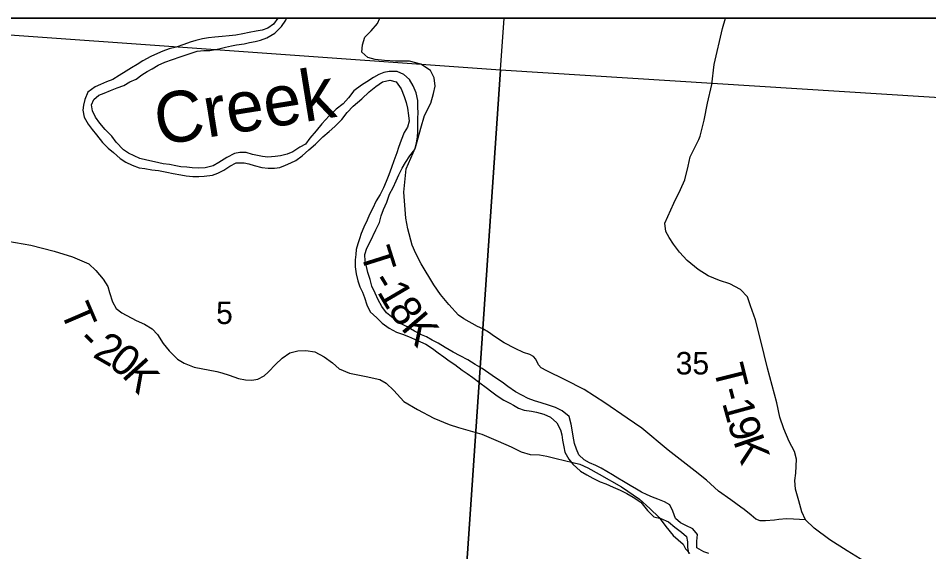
# Model space of a CAD drawing. Extents: x 0 to 34, y 0 to 22.
# Drawn here: x 3.709 to 5.404, y 19.906 to 20.9 of the extents above; entities that cross this region are included whole.
import ezdxf

# ---------------------------------------------------------------- set-up
doc = ezdxf.new("R2010")
doc.units = 0
for name, color, linetype in [('GM_X_Corporation', 7, 'Continuous'), ('GM_X_Major_River', 7, 'Continuous'), ('GM_X_Major_River_Text', 7, 'Continuous'), ('GM_X_Section_Text', 7, 'Continuous'), ('GM_X_Township_Road', 7, 'Continuous'), ('GM_X_Township_Road_Text', 7, 'Continuous'), ('SH_Data', 7, 'Continuous')]:
    doc.layers.add(name, color=color, linetype=linetype)

msp = doc.modelspace()

# ---------------------------------------------------------------- linework, layer by layer
at = {"layer": 'GM_X_Corporation'}
msp.add_lwpolyline([(6.4774, 18.0202), (6.488, 18.1751), (6.5242, 18.7061), (6.5297, 18.7882), (6.5448, 18.981), (6.5455, 18.9878), (6.5461, 19.0017), (6.5463, 19.0089), (6.5469, 19.0218), (6.548, 19.0466), (6.5487, 19.0617), (6.5495, 19.082), (6.5503, 19.0966), (6.5514, 19.1091), (6.5523, 19.1179), (6.5529, 19.1264), (6.5537, 19.1382), (6.5541, 19.1447), (6.5536, 19.1514), (6.5814, 19.5334), (6.6608, 20.6694), (6.6768, 20.9), (2.1, 20.9), (2.1, 14.1)], dxfattribs=at)
for points in [[(4.614, 20.9), (3.608, 20.9), (3.6063, 20.8752), (4.607, 20.8038)], [(4.607, 20.8038), (4.5379, 19.7849), (3.5308, 19.8461), (3.6063, 20.8752)], [(5.6414, 20.7385), (5.5693, 19.7272), (4.5379, 19.7849), (4.607, 20.8038)]]:
    msp.add_lwpolyline(points, close=True, dxfattribs=at)
at = {"layer": 'GM_X_Major_River'}
for points in [[(4.1927, 20.9), (4.1845, 20.8889), (4.1739, 20.8813), (4.1636, 20.8775), (4.1522, 20.8756), (4.1393, 20.8734), (4.1276, 20.8707), (4.1147, 20.8685), (4.1021, 20.867), (4.0892, 20.8658), (4.0752, 20.8647), (4.0638, 20.8632), (4.0524, 20.8613), (4.0399, 20.8587), (4.0297, 20.8552), (4.0175, 20.8511), (4.0031, 20.8458), (3.9906, 20.8427), (3.9788, 20.8386), (3.9686, 20.834), (3.9564, 20.8287), (3.9416, 20.8204), (3.9306, 20.8139), (3.92, 20.8075), (3.9101, 20.8014), (3.8972, 20.7935), (3.8854, 20.7859), (3.8737, 20.7813), (3.8623, 20.7764), (3.8524, 20.7719), (3.8391, 20.7624), (3.8331, 20.7483), (3.8308, 20.7381), (3.8296, 20.7286), (3.8323, 20.7157), (3.8399, 20.7024), (3.8471, 20.6929), (3.8554, 20.683), (3.8664, 20.6686), (3.8767, 20.6576), (3.8869, 20.6499), (3.8994, 20.6389), (3.9097, 20.6317), (3.9214, 20.6264), (3.9347, 20.6214), (3.9449, 20.6199), (3.9582, 20.6176), (3.9707, 20.6161), (3.9863, 20.6134), (3.9977, 20.6107), (4.0121, 20.6081), (4.0223, 20.6065), (4.0345, 20.6054), (4.0455, 20.605), (4.0553, 20.6057), (4.0713, 20.6076), (4.0811, 20.6114), (4.0922, 20.6171), (4.1032, 20.6243), (4.1153, 20.6304), (4.1297, 20.6304), (4.1388, 20.6285), (4.1487, 20.6254), (4.1627, 20.6216), (4.1745, 20.6208), (4.1863, 20.6204), (4.1961, 20.622), (4.2071, 20.6261), (4.2166, 20.6307), (4.2261, 20.6352), (4.2382, 20.6439), (4.2504, 20.6546), (4.2629, 20.6656), (4.2766, 20.6788), (4.288, 20.6887), (4.299, 20.6982), (4.3119, 20.7111), (4.3218, 20.724), (4.3328, 20.7361), (4.3487, 20.7498), (4.3628, 20.7631), (4.3749, 20.7729), (4.3874, 20.7813), (4.4011, 20.7843), (4.4132, 20.7812), (4.4223, 20.7683), (4.428, 20.7539), (4.4314, 20.7429), (4.4337, 20.7322), (4.436, 20.7189), (4.4371, 20.7079), (4.4341, 20.6969)], [(4.4534, 20.7341), (4.4531, 20.7466), (4.45, 20.7611), (4.4447, 20.774), (4.4379, 20.7858), (4.4269, 20.7953), (4.4148, 20.8006), (4.4, 20.8006), (4.3901, 20.7987), (4.3806, 20.7949), (4.3704, 20.7892), (4.3582, 20.7817), (4.3483, 20.7752), (4.3339, 20.7646), (4.3244, 20.7517), (4.3142, 20.7403), (4.3009, 20.7305), (4.288, 20.7183), (4.2743, 20.7031), (4.2637, 20.6902), (4.2519, 20.6762), (4.2439, 20.6656), (4.2333, 20.6595), (4.2208, 20.6508), (4.2102, 20.6466), (4.1976, 20.6436), (4.1878, 20.6421), (4.1741, 20.641), (4.1643, 20.6421), (4.1453, 20.6463), (4.1339, 20.6497), (4.1218, 20.6501), (4.1119, 20.6478), (4.0975, 20.6403), (4.0827, 20.6312), (4.072, 20.6251), (4.0576, 20.6213), (4.0455, 20.6206), (4.033, 20.6213), (4.0235, 20.6225), (4.0121, 20.6233), (4.0026, 20.6252), (3.9909, 20.6275), (3.9791, 20.629), (3.9628, 20.6324), (3.9487, 20.6355), (3.9358, 20.6389), (3.9146, 20.6488), (3.9051, 20.6549), (3.8915, 20.6693), (3.8835, 20.6803), (3.871, 20.6929), (3.8615, 20.7043), (3.8535, 20.7157), (3.8475, 20.7274), (3.846, 20.7388), (3.8501, 20.7487), (3.8596, 20.7563), (3.8695, 20.7601), (3.8809, 20.7654), (3.8938, 20.7703), (3.9059, 20.7745), (3.9173, 20.7813), (3.9287, 20.7866), (3.9393, 20.7942), (3.9492, 20.8006), (3.9587, 20.8059), (3.9701, 20.8124), (3.9822, 20.8181), (3.9963, 20.823), (4.0111, 20.8279), (4.024, 20.8321), (4.0422, 20.8385), (4.0551, 20.8397), (4.0661, 20.84), (4.0828, 20.8427), (4.0953, 20.8457), (4.1063, 20.8483), (4.1158, 20.8502), (4.1298, 20.8521), (4.1397, 20.8544), (4.1503, 20.8563), (4.1602, 20.8589), (4.1723, 20.8635), (4.1871, 20.8722), (4.1993, 20.8843), (4.2073, 20.8961), (4.2088, 20.9)], [(4.9949, 19.9028), (4.9854, 19.9062), (4.9728, 19.9134), (4.9725, 19.926), (4.9736, 19.9381), (4.9653, 19.9491), (4.952, 19.9548), (4.9421, 19.9598), (4.9327, 19.9678), (4.9281, 19.9818), (4.922, 19.9936), (4.9122, 19.9993), (4.8997, 20.0043), (4.8898, 20.0081), (4.8799, 20.0123), (4.8697, 20.0172), (4.8602, 20.0229), (4.8485, 20.0298), (4.8363, 20.037), (4.8257, 20.0434), (4.8158, 20.0495), (4.8048, 20.0556), (4.7942, 20.0617), (4.7847, 20.0666), (4.773, 20.072), (4.7627, 20.0773), (4.7529, 20.0868), (4.7483, 20.0971), (4.7449, 20.1077), (4.7426, 20.1214), (4.7407, 20.1331), (4.7385, 20.1438), (4.7347, 20.1578), (4.7218, 20.1685), (4.7093, 20.1749), (4.6964, 20.1791), (4.6827, 20.1837), (4.6706, 20.1875), (4.6584, 20.1917), (4.6349, 20.2039), (4.6209, 20.2137), (4.6099, 20.2221), (4.5977, 20.2301), (4.5856, 20.2388), (4.5727, 20.2472), (4.5598, 20.2548), (4.5462, 20.2636), (4.5321, 20.2708), (4.5192, 20.278), (4.5044, 20.2868), (4.4912, 20.2944), (4.4802, 20.3001), (4.4695, 20.3065), (4.4601, 20.3103), (4.4472, 20.3172), (4.4324, 20.3259), (4.4225, 20.3309), (4.4073, 20.3411), (4.3952, 20.351), (4.3865, 20.3628), (4.3793, 20.3754), (4.374, 20.3879), (4.3679, 20.4008), (4.3645, 20.413), (4.3603, 20.4262), (4.3577, 20.4376), (4.3554, 20.4471), (4.3546, 20.46), (4.3584, 20.4714), (4.3645, 20.4836), (4.3752, 20.5056), (4.3816, 20.5193), (4.385, 20.5318), (4.3892, 20.5436), (4.3957, 20.5576), (4.4006, 20.572), (4.4071, 20.5845), (4.4128, 20.5971), (4.4181, 20.6085), (4.4242, 20.6206), (4.4302, 20.6312), (4.4386, 20.6438), (4.4477, 20.6555), (4.4507, 20.6677), (4.4523, 20.6791), (4.453, 20.6885), (4.453, 20.7136), (4.4538, 20.7235), (4.4534, 20.7341)], [(4.4341, 20.6969), (4.4276, 20.6871), (4.4223, 20.6726), (4.4173, 20.659), (4.4143, 20.6491), (4.4086, 20.6343), (4.404, 20.6221), (4.3991, 20.6085), (4.3945, 20.5956), (4.3896, 20.5842), (4.3828, 20.5717), (4.3759, 20.5595), (4.3687, 20.5451), (4.3634, 20.5341), (4.3588, 20.5238), (4.3528, 20.5109), (4.3478, 20.4988), (4.3448, 20.4893), (4.3418, 20.4794), (4.3387, 20.4692), (4.3376, 20.4597), (4.3364, 20.4498), (4.3368, 20.4369), (4.3387, 20.4236), (4.3417, 20.4107), (4.3451, 20.3993), (4.3504, 20.3898), (4.3542, 20.3795), (4.3584, 20.3659), (4.3645, 20.3533), (4.3766, 20.3419), (4.3868, 20.3321), (4.4001, 20.3225), (4.4138, 20.3153), (4.4244, 20.3115), (4.4358, 20.307), (4.4468, 20.302), (4.4581, 20.2971), (4.468, 20.2925), (4.4805, 20.2849), (4.4908, 20.2769), (4.5014, 20.2693), (4.5113, 20.2617), (4.5223, 20.2548), (4.5355, 20.2446), (4.545, 20.2381), (4.5553, 20.2309), (4.5685, 20.221), (4.5803, 20.2119), (4.5909, 20.2039), (4.6008, 20.1967), (4.6133, 20.1883), (4.6243, 20.1826), (4.6313, 20.1792)], [(4.6313, 20.1792), (4.6406, 20.1735), (4.6512, 20.1701), (4.6649, 20.1681), (4.6744, 20.1662), (4.688, 20.1624), (4.7002, 20.1571), (4.7119, 20.1465), (4.7187, 20.1335), (4.721, 20.1237), (4.7225, 20.1138), (4.7248, 20.1016), (4.7271, 20.0914), (4.7343, 20.0785), (4.7415, 20.069), (4.7559, 20.0564), (4.768, 20.0492), (4.779, 20.0431), (4.7927, 20.0366), (4.8029, 20.0328), (4.817, 20.0267), (4.8299, 20.021), (4.8424, 20.0149), (4.8541, 20.0081), (4.8682, 19.9986), (4.8807, 19.983), (4.8924, 19.9709), (4.9057, 19.9678), (4.9198, 19.9617), (4.9315, 19.9518), (4.944, 19.9427), (4.9535, 19.9347), (4.955, 19.9248), (4.9554, 19.9146), (4.9569, 19.9028)]]:
    msp.add_lwpolyline(points, dxfattribs=at)
at = {"layer": 'GM_X_Township_Road'}
for points in [[(5.0546, 19.9895), (5.0357, 20.0027), (5.0128, 20.0193), (4.9905, 20.0393), (4.9696, 20.0565), (4.9189, 20.0953), (4.8704, 20.1364), (4.843, 20.1549), (4.8016, 20.1835), (4.763, 20.2082), (4.7272, 20.2261), (4.6931, 20.2433), (4.6829, 20.2486), (4.6781, 20.2545), (4.6728, 20.2651), (4.6686, 20.27), (4.6615, 20.2737), (4.6497, 20.2773), (4.6344, 20.2845), (4.6137, 20.2951), (4.5962, 20.307), (4.585, 20.3152), (4.5744, 20.3211), (4.564, 20.3256), (4.5391, 20.3397), (4.5288, 20.3467), (4.5111, 20.3666), (4.4957, 20.3853), (4.4829, 20.4032), (4.4597, 20.4424), (4.4494, 20.4614), (4.4428, 20.4775), (4.4344, 20.5077), (4.4309, 20.5273), (4.4274, 20.5761), (4.4313, 20.6195), (4.4491, 20.6589), (4.4589, 20.6953), (4.4658, 20.719), (4.4776, 20.7417), (4.4826, 20.7594), (4.4855, 20.7732), (4.4836, 20.789), (4.4767, 20.8028), (4.4589, 20.8146), (4.4374, 20.8198), (4.4117, 20.8202), (4.391, 20.8214), (4.3739, 20.8232), (4.3603, 20.8267), (4.3491, 20.8367), (4.3502, 20.8503), (4.3544, 20.8645), (4.3662, 20.8763), (4.378, 20.8899), (4.3822, 20.9)], [(5.2844, 19.8879), (5.2525, 19.9079), (5.2202, 19.9283), (5.1907, 19.9503), (5.1749, 19.9659), (5.1682, 19.9806), (5.1622, 20.001), (5.156, 20.0226), (5.1552, 20.0389), (5.1569, 20.0525), (5.158, 20.0784), (5.1543, 20.0928), (5.1445, 20.1118), (5.1347, 20.1352), (5.1271, 20.1571), (5.1212, 20.1833), (5.1039, 20.248), (5.0917, 20.2989), (5.0816, 20.338), (5.0726, 20.3645), (5.0667, 20.381), (5.0536, 20.3946), (5.034, 20.4053), (5.0146, 20.4114), (4.9935, 20.42), (4.9748, 20.4317), (4.9545, 20.4488), (4.9402, 20.4641), (4.9288, 20.4789), (4.921, 20.4912), (4.9149, 20.5026), (4.9129, 20.5184), (4.9298, 20.5554), (4.942, 20.581), (4.95, 20.5989), (4.9565, 20.6245), (4.9604, 20.6415), (4.966, 20.6528), (4.9761, 20.6739), (4.979, 20.6804), (4.9859, 20.71), (4.9927, 20.742), (5.0004, 20.7767), (5.0049, 20.814), (5.0202, 20.8808), (5.0257, 20.9)], [(3.6898, 20.4846), (3.7328, 20.4773), (3.7766, 20.466), (3.8102, 20.4557), (3.8406, 20.4427), (3.8536, 20.43), (3.8676, 20.4139), (3.876, 20.4005), (3.8793, 20.389), (3.8849, 20.3719), (3.8919, 20.3592), (3.9024, 20.3509), (3.9289, 20.3367), (3.9443, 20.3302), (3.9587, 20.3213), (3.9684, 20.311), (3.9793, 20.2942), (3.9906, 20.2806), (4.0059, 20.2647), (4.018, 20.2575), (4.0371, 20.2501), (4.0789, 20.2417), (4.0882, 20.2394), (4.1019, 20.2349), (4.1197, 20.2289), (4.1326, 20.2262), (4.1443, 20.226), (4.1554, 20.2279), (4.1672, 20.2337), (4.1744, 20.2404), (4.1753, 20.2412), (4.188, 20.255), (4.2007, 20.2668), (4.2149, 20.2764), (4.2297, 20.2804), (4.245, 20.281), (4.2618, 20.2785), (4.2791, 20.2695), (4.2945, 20.2583), (4.3067, 20.247), (4.3262, 20.239), (4.3569, 20.2326), (4.3822, 20.2271), (4.3943, 20.2199), (4.4085, 20.2063), (4.4269, 20.1861), (4.4526, 20.1713), (4.483, 20.1548), (4.5118, 20.1429), (4.5287, 20.1378), (4.5721, 20.1254), (4.6026, 20.1122), (4.6267, 20.1015), (4.6454, 20.0923), (4.6623, 20.0876), (4.6797, 20.0865), (4.6931, 20.0843), (4.711, 20.0801), (4.7417, 20.0723), (4.7549, 20.069), (4.7695, 20.0624), (4.7905, 20.0509), (4.8322, 20.0269), (4.8656, 20.0038), (4.8849, 19.9869), (4.9026, 19.9698), (4.9147, 19.9534), (4.9287, 19.9367), (4.9472, 19.9201), (4.9514, 19.9118), (4.9592, 19.903)], [(5.1749, 19.9659), (5.1526, 19.967), (5.1394, 19.9676), (5.1251, 19.9662), (5.1169, 19.9652), (5.1001, 19.9637), (5.0904, 19.9639), (5.0823, 19.9666), (5.0739, 19.9743), (5.0609, 19.9851), (5.0546, 19.9895)]]:
    msp.add_lwpolyline(points, dxfattribs=at)
at = {"layer": 'SH_Data'}
msp.add_line((2.1, 20.9), (8.9, 20.9), dxfattribs=at)

# ---------------------------------------------------------------- texts
at = {"layer": 'GM_X_Major_River_Text'}
msp.add_text('Creek', height=0.0947, rotation=9.122, dxfattribs=at).set_placement((3.9708, 20.6629))
at = {"layer": 'GM_X_Section_Text'}
for s, height, p in [('5', 0.0419, (4.0777, 20.3303)), ('35', 0.04186, (4.9332, 20.2364))]:
    msp.add_text(s, height=height, rotation=0, dxfattribs=at).set_placement(p)
at = {"layer": 'GM_X_Township_Road_Text'}
for s, rotation, p in [('T', 287.6069, (4.3456, 20.4639)), ('1', 300.4265, (4.3764, 20.3903)), ('-', 301.1629, (4.3645, 20.4101)), ('T', 293.2706, (3.7867, 20.3548)), ('8', 304.2835, (4.3964, 20.3566)), ('K', 310.4698, (4.4202, 20.3223)), ('-', 314.958, (3.8166, 20.2965)), ('2', 330.239, (3.8462, 20.2699)), ('0', 322.4244, (3.8748, 20.2537)), ('K', 311.8998, (3.9006, 20.2342)), ('T', 284.0695, (5.0028, 20.2487)), ('-', 284.3967, (5.0132, 20.2072)), ('1', 285.3173, (5.0193, 20.1836)), ('9', 286.8387, (5.029, 20.1483)), ('K', 289.1204, (5.0399, 20.1124))]:
    msp.add_text(s, height=0.0568, rotation=rotation, dxfattribs=at).set_placement(p)

doc.saveas('drawing.dxf')
